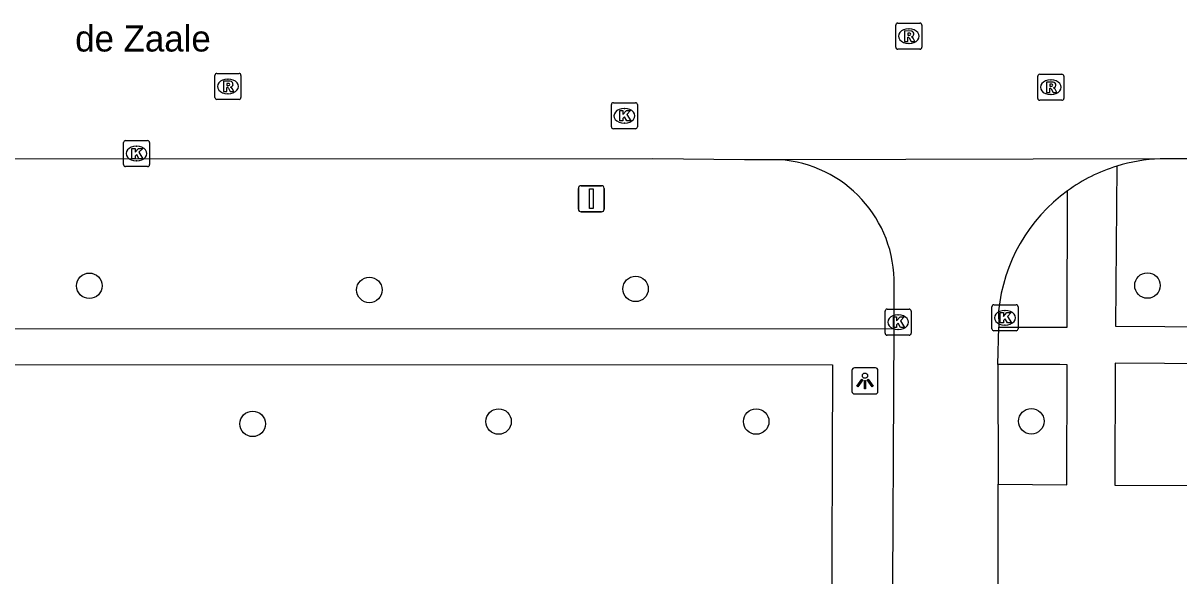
# Model space of a CAD drawing. Extents: x 161477 to 163040, y 383680 to 384868.
# Drawn here: x 162308.22 to 162352.59, y 384355.8 to 384377.01 of the extents above; entities that cross this region are included whole.
import ezdxf

# ---------------------------------------------------------------- set-up
doc = ezdxf.new("R2010")
doc.units = 0
for name, color, linetype in [('IMGEO_Boom', 7, 'Continuous'), ('IMGEO_Kolk', 7, 'Continuous'), ('IMGEO_Lichtpunt', 7, 'Continuous'), ('IMGEO_Openbare_ruimte_label', 7, 'Continuous'), ('IMGEO_Rijbaan_lokaal_open', 7, 'Continuous'), ('IMGEO_Rioolput', 7, 'Continuous'), ('IMGEO_Verkeersbordpaal', 7, 'Continuous'), ('IMGEO_Voetpad_open', 7, 'Continuous')]:
    doc.layers.add(name, color=color, linetype=linetype)

msp = doc.modelspace()

# ---------------------------------------------------------------- linework, layer by layer
at = {"layer": 'IMGEO_Boom'}
for centre in [(162310.76, 384366.93), (162321.51, 384366.77), (162331.73, 384366.81), (162351.38, 384366.94), (162317.03, 384361.63), (162326.47, 384361.72), (162336.36, 384361.72), (162346.92, 384361.73)]:
    msp.add_circle(centre, 0.489, dxfattribs=at)
at = {"layer": 'IMGEO_Kolk'}
for p, q in [((162330.801, 384373.03), (162330.801, 384373.882)), ((162330.876, 384373.956), (162331.728, 384373.956)), ((162331.802, 384373.882), (162331.802, 384373.03)), ((162331.289, 384373.736), (162331.314, 384373.736)), ((162331.728, 384372.956), (162330.876, 384372.956)), ((162331.312, 384373.176), (162331.287, 384373.176)), ((162312.146, 384372.505), (162312.998, 384372.505)), ((162312.071, 384371.579), (162312.071, 384372.431)), ((162312.559, 384372.285), (162312.584, 384372.285)), ((162313.072, 384372.431), (162313.072, 384371.579)), ((162312.582, 384371.725), (162312.557, 384371.725)), ((162312.998, 384371.505), (162312.146, 384371.505)), ((162341.308, 384365.107), (162341.308, 384365.959)), ((162341.383, 384366.033), (162342.235, 384366.033)), ((162341.796, 384365.813), (162341.821, 384365.813)), ((162342.309, 384365.959), (162342.309, 384365.107)), ((162345.41, 384365.276), (162345.41, 384366.128)), ((162345.485, 384366.202), (162346.337, 384366.202)), ((162345.898, 384365.982), (162345.923, 384365.982)), ((162346.411, 384366.128), (162346.411, 384365.276)), ((162345.921, 384365.422), (162345.896, 384365.422)), ((162342.235, 384365.033), (162341.383, 384365.033)), ((162341.819, 384365.253), (162341.794, 384365.253)), ((162346.337, 384365.202), (162345.485, 384365.202))]:
    msp.add_line(p, q, dxfattribs=at)
for points in [[(162330.801, 384373.03), (162330.801, 384373.882)], [(162330.876, 384373.956), (162331.728, 384373.956)], [(162331.802, 384373.882), (162331.802, 384373.03)], [(162331.122, 384373.656), (162331.245, 384373.656), (162331.245, 384373.505), (162331.375, 384373.656), (162331.539, 384373.656), (162331.393, 384373.505), (162331.546, 384373.256), (162331.394, 384373.256), (162331.309, 384373.42), (162331.245, 384373.353), (162331.245, 384373.256), (162331.122, 384373.256), (162331.122, 384373.656)], [(162331.728, 384372.956), (162330.876, 384372.956)], [(162312.146, 384372.505), (162312.998, 384372.505)], [(162312.071, 384371.579), (162312.071, 384372.431)], [(162312.392, 384372.205), (162312.515, 384372.205), (162312.515, 384372.054), (162312.645, 384372.205), (162312.809, 384372.205), (162312.663, 384372.054), (162312.816, 384371.805), (162312.664, 384371.805), (162312.579, 384371.969), (162312.515, 384371.902), (162312.515, 384371.805), (162312.392, 384371.805), (162312.392, 384372.205)], [(162313.072, 384372.431), (162313.072, 384371.579)], [(162312.998, 384371.505), (162312.146, 384371.505)], [(162341.308, 384365.107), (162341.308, 384365.959)], [(162341.383, 384366.033), (162342.235, 384366.033)], [(162342.309, 384365.959), (162342.309, 384365.107)], [(162345.41, 384365.276), (162345.41, 384366.128)], [(162345.485, 384366.202), (162346.337, 384366.202)], [(162345.731, 384365.902), (162345.854, 384365.902), (162345.854, 384365.751), (162345.984, 384365.902), (162346.148, 384365.902), (162346.002, 384365.751), (162346.155, 384365.502), (162346.003, 384365.502), (162345.918, 384365.666), (162345.854, 384365.599), (162345.854, 384365.502), (162345.731, 384365.502), (162345.731, 384365.902)], [(162346.411, 384366.128), (162346.411, 384365.276)], [(162341.629, 384365.733), (162341.752, 384365.733), (162341.752, 384365.582), (162341.882, 384365.733), (162342.046, 384365.733), (162341.9, 384365.582), (162342.053, 384365.333), (162341.901, 384365.333), (162341.816, 384365.497), (162341.752, 384365.43), (162341.752, 384365.333), (162341.629, 384365.333), (162341.629, 384365.733)], [(162342.235, 384365.033), (162341.383, 384365.033)], [(162346.337, 384365.202), (162345.485, 384365.202)]]:
    msp.add_lwpolyline(points, dxfattribs=at)
for centre, start, end in [((162330.878, 384373.88), 91.552, 178.448), ((162330.878, 384373.88), 91.552, 178.448), ((162331.726, 384373.88), 1.552, 88.448), ((162331.726, 384373.88), 1.552, 88.448), ((162330.878, 384373.032), 181.552, 268.448), ((162330.878, 384373.032), 181.552, 268.448), ((162331.726, 384373.032), 271.552, 358.448), ((162331.726, 384373.032), 271.552, 358.448), ((162312.148, 384372.429), 91.552, 178.448), ((162312.148, 384372.429), 91.552, 178.448), ((162312.996, 384372.429), 1.552, 88.448), ((162312.996, 384372.429), 1.552, 88.448), ((162312.148, 384371.581), 181.552, 268.448), ((162312.148, 384371.581), 181.552, 268.448), ((162312.996, 384371.581), 271.552, 358.448), ((162312.996, 384371.581), 271.552, 358.448), ((162341.385, 384365.957), 91.552, 178.448), ((162341.385, 384365.957), 91.552, 178.448), ((162342.233, 384365.957), 1.552, 88.448), ((162342.233, 384365.957), 1.552, 88.448), ((162345.487, 384366.126), 91.552, 178.448), ((162345.487, 384366.126), 91.552, 178.448), ((162346.335, 384366.126), 1.552, 88.448), ((162346.335, 384366.126), 1.552, 88.448), ((162341.385, 384365.109), 181.552, 268.448), ((162341.385, 384365.109), 181.552, 268.448), ((162342.233, 384365.109), 271.552, 358.448), ((162342.233, 384365.109), 271.552, 358.448), ((162345.487, 384365.278), 181.552, 268.448), ((162345.487, 384365.278), 181.552, 268.448), ((162346.335, 384365.278), 271.552, 358.448), ((162346.335, 384365.278), 271.552, 358.448)]:
    msp.add_arc(centre, 0.0765, start, end, dxfattribs=at)
for centre, major_axis, ratio, start_param, end_param in [((162331.288, 384373.456), (-0.387, 0.002), 0.722429, 4.712389, 7.853982), ((162331.313, 384373.456), (-0.39, 0.002), 0.717154, 1.570796, 4.712389), ((162312.558, 384372.005), (-0.387, 0.002), 0.722429, 4.712389, 7.853982), ((162312.583, 384372.005), (-0.39, 0.002), 0.717154, 1.570796, 4.712389), ((162341.795, 384365.533), (-0.387, 0.002), 0.722429, 4.712389, 7.853982), ((162341.82, 384365.533), (-0.39, 0.002), 0.717154, 1.570796, 4.712389), ((162345.897, 384365.702), (-0.387, 0.002), 0.722429, 4.712389, 7.853982), ((162345.922, 384365.702), (-0.39, 0.002), 0.717154, 1.570796, 4.712389)]:
    msp.add_ellipse(centre, major_axis=major_axis, ratio=ratio, start_param=start_param, end_param=end_param, dxfattribs=at)
at = {"layer": 'IMGEO_Lichtpunt'}
for p, q in [((162340.037, 384363.683), (162340.037, 384362.876)), ((162340.037, 384363.683), (162340.037, 384362.876)), ((162340.939, 384363.778), (162340.131, 384363.778)), ((162340.939, 384363.778), (162340.131, 384363.778)), ((162341.033, 384362.876), (162341.033, 384363.683)), ((162341.033, 384362.876), (162341.033, 384363.683)), ((162340.131, 384362.782), (162340.939, 384362.782)), ((162340.131, 384362.782), (162340.939, 384362.782))]:
    msp.add_line(p, q, dxfattribs=at)
for points in [[(162340.411, 384363.347), (162340.45, 384363.319), (162340.262, 384363.057), (162340.224, 384363.084), (162340.411, 384363.347)], [(162340.513, 384363.299), (162340.56, 384363.299), (162340.56, 384362.977), (162340.513, 384362.977), (162340.513, 384363.299)], [(162340.623, 384363.319), (162340.661, 384363.346), (162340.848, 384363.084), (162340.809, 384363.056), (162340.623, 384363.319)]]:
    msp.add_lwpolyline(points, dxfattribs=at)
msp.add_circle((162340.536, 384363.481), 0.0994, dxfattribs=at)
for centre, start, end in [((162340.131, 384363.683), 90, 180), ((162340.131, 384363.683), 90, 180), ((162340.939, 384363.683), 0, 90), ((162340.939, 384363.683), 0, 90), ((162340.131, 384362.876), 180, 270), ((162340.131, 384362.876), 180, 270), ((162340.939, 384362.876), 270, 0), ((162340.939, 384362.876), 270, 360)]:
    msp.add_arc(centre, 0.0946, start, end, dxfattribs=at)
at = {"layer": 'IMGEO_Rijbaan_lokaal_open'}
for points in [[(162337.233, 384371.769), (162336.121, 384371.767), (162335.917, 384371.768), (162332.391, 384371.802), (162306.88, 384371.793), (162291.306, 384371.803), (162285.506, 384371.799), (162283.369, 384371.791), (162270.638, 384371.806), (162249.182, 384371.787), (162247.174, 384373.809), (162246.62, 384373.804), (162235.562, 384371.78), (162235.194, 384371.776)], [(162351.862, 384371.801), (162337.233, 384371.769)], [(162423.885, 384371.708), (162422.293, 384371.749), (162409.717, 384371.797), (162394.185, 384371.816), (162373.552, 384371.801), (162351.862, 384371.801)], [(162341.652, 384365.285), (162341.652, 384366.944)], [(162345.665, 384365.965), (162345.672, 384365.339)], [(162341.598, 384353.057), (162341.652, 384365.285)], [(162345.641, 384363.913), (162345.672, 384365.339)], [(162345.641, 384363.913), (162345.646, 384359.322)], [(162345.575, 384300.82), (162345.575, 384301.098), (162345.586, 384326.11), (162345.645, 384352.813), (162345.646, 384359.322)]]:
    msp.add_lwpolyline(points, dxfattribs=at)
for centre, radius, start, end in [((162336.934, 384367.059), 4.72, 358.6069, 86.3634), ((162352.099, 384365.376), 6.429, 92.1145, 107.1352), ((162352.103, 384365.339), 6.466, 107.0713, 125.8646), ((162352.107, 384365.333), 6.472, 125.8594, 174.3997)]:
    msp.add_arc(centre, radius, start, end, dxfattribs=at)
at = {"layer": 'IMGEO_Rioolput'}
for p, q in [((162341.719, 384376.084), (162341.719, 384376.936)), ((162341.794, 384377.01), (162342.646, 384377.01)), ((162342.72, 384376.936), (162342.72, 384376.084)), ((162342.207, 384376.79), (162342.232, 384376.79)), ((162342.23, 384376.23), (162342.205, 384376.23)), ((162342.646, 384376.01), (162341.794, 384376.01)), ((162315.579, 384374.154), (162315.579, 384375.006)), ((162315.654, 384375.08), (162316.506, 384375.08)), ((162316.067, 384374.86), (162316.092, 384374.86)), ((162316.58, 384375.006), (162316.58, 384374.154)), ((162347.169, 384374.124), (162347.169, 384374.976)), ((162347.244, 384375.05), (162348.096, 384375.05)), ((162347.657, 384374.83), (162347.682, 384374.83)), ((162348.17, 384374.976), (162348.17, 384374.124)), ((162316.09, 384374.3), (162316.065, 384374.3)), ((162347.68, 384374.27), (162347.655, 384374.27)), ((162316.506, 384374.08), (162315.654, 384374.08)), ((162348.096, 384374.05), (162347.244, 384374.05))]:
    msp.add_line(p, q, dxfattribs=at)
for points in [[(162341.719, 384376.084), (162341.719, 384376.936)], [(162341.794, 384377.01), (162342.646, 384377.01)], [(162342.72, 384376.936), (162342.72, 384376.084)], [(162342.308, 384376.708), (162342.056, 384376.71), (162342.056, 384376.31)], [(162342.056, 384376.31), (162342.18, 384376.31), (162342.18, 384376.472), (162342.191, 384376.472)], [(162342.234, 384376.629), (162342.18, 384376.629), (162342.18, 384376.548)], [(162342.18, 384376.548), (162342.232, 384376.548)], [(162342.238, 384376.443), (162342.309, 384376.31), (162342.449, 384376.31), (162342.384, 384376.436)], [(162342.646, 384376.01), (162341.794, 384376.01)], [(162315.579, 384374.154), (162315.579, 384375.006)], [(162315.654, 384375.08), (162316.506, 384375.08)], [(162316.168, 384374.778), (162315.916, 384374.78), (162315.916, 384374.38)], [(162316.094, 384374.699), (162316.04, 384374.699), (162316.04, 384374.618)], [(162316.58, 384375.006), (162316.58, 384374.154)], [(162347.169, 384374.124), (162347.169, 384374.976)], [(162347.244, 384375.05), (162348.096, 384375.05)], [(162347.758, 384374.748), (162347.506, 384374.75), (162347.506, 384374.35)], [(162348.17, 384374.976), (162348.17, 384374.124)], [(162315.916, 384374.38), (162316.04, 384374.38), (162316.04, 384374.542), (162316.051, 384374.542)], [(162316.04, 384374.618), (162316.092, 384374.618)], [(162316.098, 384374.513), (162316.169, 384374.38), (162316.309, 384374.38), (162316.244, 384374.506)], [(162347.506, 384374.35), (162347.63, 384374.35), (162347.63, 384374.512), (162347.641, 384374.512)], [(162347.684, 384374.669), (162347.63, 384374.669), (162347.63, 384374.588)], [(162347.63, 384374.588), (162347.682, 384374.588)], [(162347.688, 384374.483), (162347.759, 384374.35), (162347.899, 384374.35), (162347.834, 384374.476)], [(162316.506, 384374.08), (162315.654, 384374.08)], [(162348.096, 384374.05), (162347.244, 384374.05)]]:
    msp.add_lwpolyline(points, dxfattribs=at)
for centre, radius, start, end in [((162341.796, 384376.934), 0.0765, 91.552, 178.448), ((162341.796, 384376.934), 0.0765, 91.552, 178.448), ((162342.644, 384376.934), 0.0765, 1.552, 88.448), ((162342.644, 384376.934), 0.0765, 1.552, 88.448), ((162342.19, 384376.419), 0.0533, 26.0293, 88.6989), ((162342.216, 384376.737), 0.19, 274.7715, 282.9687), ((162342.24, 384376.533), 0.0964, 77.0061, 93.1865), ((162342.254, 384376.59), 0.0378, 276.6634, 79.6772), ((162342.307, 384376.598), 0.109, 350.3612, 89.416), ((162342.305, 384376.598), 0.112, 277.5842, 350.9817), ((162342.289, 384376.383), 0.108, 29.5134, 73.7905), ((162341.796, 384376.086), 0.0765, 181.552, 268.448), ((162341.796, 384376.086), 0.0765, 181.552, 268.448), ((162342.644, 384376.086), 0.0765, 271.552, 358.448), ((162342.644, 384376.086), 0.0765, 271.552, 358.448), ((162315.656, 384375.004), 0.0765, 91.552, 178.448), ((162315.656, 384375.004), 0.0765, 91.552, 178.448), ((162316.1, 384374.603), 0.0964, 77.0061, 93.1865), ((162316.114, 384374.66), 0.0378, 276.6634, 79.6772), ((162316.167, 384374.668), 0.109, 350.3612, 89.416), ((162316.504, 384375.004), 0.0765, 1.552, 88.448), ((162316.504, 384375.004), 0.0765, 1.552, 88.448), ((162347.246, 384374.974), 0.0765, 91.552, 178.448), ((162347.246, 384374.974), 0.0765, 91.552, 178.448), ((162347.757, 384374.638), 0.109, 350.3612, 89.416), ((162348.094, 384374.974), 0.0765, 1.552, 88.448), ((162348.094, 384374.974), 0.0765, 1.552, 88.448), ((162316.05, 384374.489), 0.0533, 26.0293, 88.6989), ((162316.076, 384374.807), 0.19, 274.7715, 282.9687), ((162316.165, 384374.668), 0.112, 277.5842, 350.9817), ((162316.149, 384374.453), 0.108, 29.5134, 73.7905), ((162347.64, 384374.459), 0.0533, 26.0293, 88.6989), ((162347.666, 384374.777), 0.19, 274.7715, 282.9687), ((162347.69, 384374.573), 0.0964, 77.0061, 93.1865), ((162347.704, 384374.63), 0.0378, 276.6634, 79.6772), ((162347.755, 384374.638), 0.112, 277.5842, 350.9817), ((162347.739, 384374.423), 0.108, 29.5134, 73.7905), ((162315.656, 384374.156), 0.0765, 181.552, 268.448), ((162315.656, 384374.156), 0.0765, 181.552, 268.448), ((162316.504, 384374.156), 0.0765, 271.552, 358.448), ((162316.504, 384374.156), 0.0765, 271.552, 358.448), ((162347.246, 384374.126), 0.0765, 181.552, 268.448), ((162347.246, 384374.126), 0.0765, 181.552, 268.448), ((162348.094, 384374.126), 0.0765, 271.552, 358.448), ((162348.094, 384374.126), 0.0765, 271.552, 358.448)]:
    msp.add_arc(centre, radius, start, end, dxfattribs=at)
for centre, major_axis, ratio, start_param, end_param in [((162342.206, 384376.51), (-0.387, 0.002), 0.722429, 4.712389, 7.853982), ((162342.231, 384376.51), (-0.39, 0.002), 0.717154, 1.570796, 4.712389), ((162316.066, 384374.58), (-0.387, 0.002), 0.722429, 4.712389, 7.853982), ((162316.091, 384374.58), (-0.39, 0.002), 0.717154, 1.570796, 4.712389), ((162347.656, 384374.55), (-0.387, 0.002), 0.722429, 4.712389, 7.853982), ((162347.681, 384374.55), (-0.39, 0.002), 0.717154, 1.570796, 4.712389)]:
    msp.add_ellipse(centre, major_axis=major_axis, ratio=ratio, start_param=start_param, end_param=end_param, dxfattribs=at)
at = {"layer": 'IMGEO_Verkeersbordpaal'}
for p, q in [((162329.635, 384370.77), (162330.425, 384370.77)), ((162330.425, 384370.77), (162329.635, 384370.77)), ((162329.535, 384369.87), (162329.535, 384370.67)), ((162329.535, 384370.67), (162329.535, 384369.87)), ((162330.525, 384370.67), (162330.525, 384369.87)), ((162330.525, 384369.87), (162330.525, 384370.67)), ((162330.425, 384369.77), (162329.635, 384369.77)), ((162329.635, 384369.77), (162330.425, 384369.77))]:
    msp.add_line(p, q, dxfattribs=at)
msp.add_lwpolyline([(162329.955, 384370.645), (162330.105, 384370.645), (162330.105, 384369.895), (162329.955, 384369.895), (162329.955, 384370.645)], dxfattribs=at)
for centre, start, end in [((162329.635, 384370.67), 90, 180), ((162329.635, 384370.67), 90, 180), ((162330.425, 384370.67), 0, 90), ((162330.425, 384370.67), 360, 90), ((162329.635, 384369.87), 180, 270), ((162329.635, 384369.87), 180, 270), ((162330.425, 384369.87), 270, 0), ((162330.425, 384369.87), 270, 0)]:
    msp.add_arc(centre, 0.1, start, end, dxfattribs=at)
at = {"layer": 'IMGEO_Voetpad_open'}
for points in [[(162350.205, 384371.52), (162350.158, 384365.377), (162425.894, 384364.863), (162425.896, 384365.557), (162425.914, 384370.45), (162425.917, 384371.315)], [(162345.672, 384365.339), (162348.091, 384365.336), (162348.301, 384365.336), (162348.315, 384370.579)], [(162235.666, 384365.194), (162260.548, 384365.225), (162295.516, 384365.277), (162341.652, 384365.285)], [(162251.684, 384355.359), (162251.669, 384360.914), (162251.661, 384363.802), (162251.801, 384363.804), (162279.217, 384363.849), (162303.94, 384363.903), (162339.295, 384363.901), (162339.245, 384353.051)], [(162345.646, 384359.322), (162348.285, 384359.292), (162348.298, 384363.902), (162348.018, 384363.903), (162345.641, 384363.913)], [(162426.026, 384342.251), (162426.025, 384343.013), (162426.009, 384351.609), (162426.015, 384362.361), (162426.015, 384363.448), (162350.145, 384363.962), (162350.123, 384359.283), (162353.385, 384359.268), (162353.319, 384354.538)]]:
    msp.add_lwpolyline(points, dxfattribs=at)

# ---------------------------------------------------------------- texts
at = {"layer": 'IMGEO_Openbare_ruimte_label'}
msp.add_text('de Zaale', height=1, dxfattribs=at).set_placement((162310.218, 384375.921))

doc.saveas('drawing.dxf')
